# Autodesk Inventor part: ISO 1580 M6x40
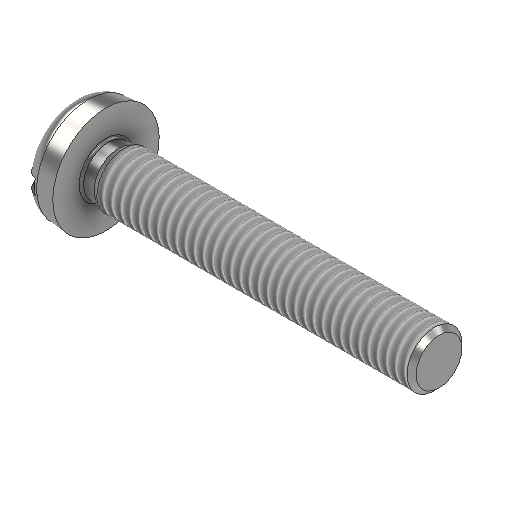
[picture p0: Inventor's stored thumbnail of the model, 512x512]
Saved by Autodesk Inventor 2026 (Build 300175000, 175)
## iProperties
Created: 2022-01
Part Number: ISO 1580 M6x40
Material: Steel, Mild
Document SubType Name: Modeling
Designer: Lars Bertram Pedersen
Density: 7.85 g/cm^3
Appearance: Semi-Polished
Author: larsb
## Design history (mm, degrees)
revolve "Revolution1" stored, may be unused: angle "d10" = 90 deg
chamfer "Chamfer1" distance "d11" = 0.5; stored, may be unused: second distance "d12" = 2, angle "d13" = 45 deg
thread "Thread1" dims "d14" = 33.902, "d15" = 0
sketch "Sketch3"
  geometry: L1 (0, -0.8)-(1.4, -0.8); L2 (1.4, -0.8)-(1.4, 0.8); L3 (1.4, 0.8)-(0, 0.8); L4 (0, 0.8)-(0, -0.8); L5 (0, -0.8)-(1.4, 0.8); L6 (1.4, -0.8)-(0, 0.8); 3 further points
  constraints: 12 end point, 3 midpoint, 2 parallel, 1 coincident, 1 horizontal, 1 perpendicular
  dimensions: "d16" = 1.6 distance of L3.end L1.start; "d17" = 1.4 distance of L2.end L3.end
extrude "Extrusion1" cut sketch "Sketch3" extent not by distance; stored distance "d18" = 10; taper "d19" = 0 deg
fillet "Fillet1" dims "d20" = 0.25
body "Solid1"
sketch "Sketch2" dims "d11" = 0.5
  geometry: L1 (0, 0)-(40, 0); L2 (0, 0)-(0, 3.832); L3 (3.6, 5.815)-(3.6, 2.69); L4 (3.6, 2.69)-(4.99, 2.69); L5 (4.99, 2.69)-(5.598, 3); L6 (5.598, 3)-(40, 3); L7 (40, 3)-(40, 0); L8 (1.661, 5.645)-(3.6, 5.815); A1 r 1.82 centre (1.82, 3.832) between (1.661, 5.645) and (0, 3.832)
  constraints: 16 end point, 2 perpendicular, 2 point on circle, 2 tangent, 2 vertical, 1 centre point, 1 horizontal, 1 parallel
  dimensions: "d0" = 40 distance of L1.start L1.end; "d2" = 1.82 radius of A1; "d3" = 5 deg angle of L8 L1; "d4" = 3.6 distance between parallel lines of L3 L2; "d5" = 11.63 diameter of L3.start L1; "d6" = 5.38 diameter of L4 L1; "d7" = 27 deg angle of L5 L4; "d8" = 6 diameter of L6 L1; "d9" = 1.39 distance of L3.end L4.end
